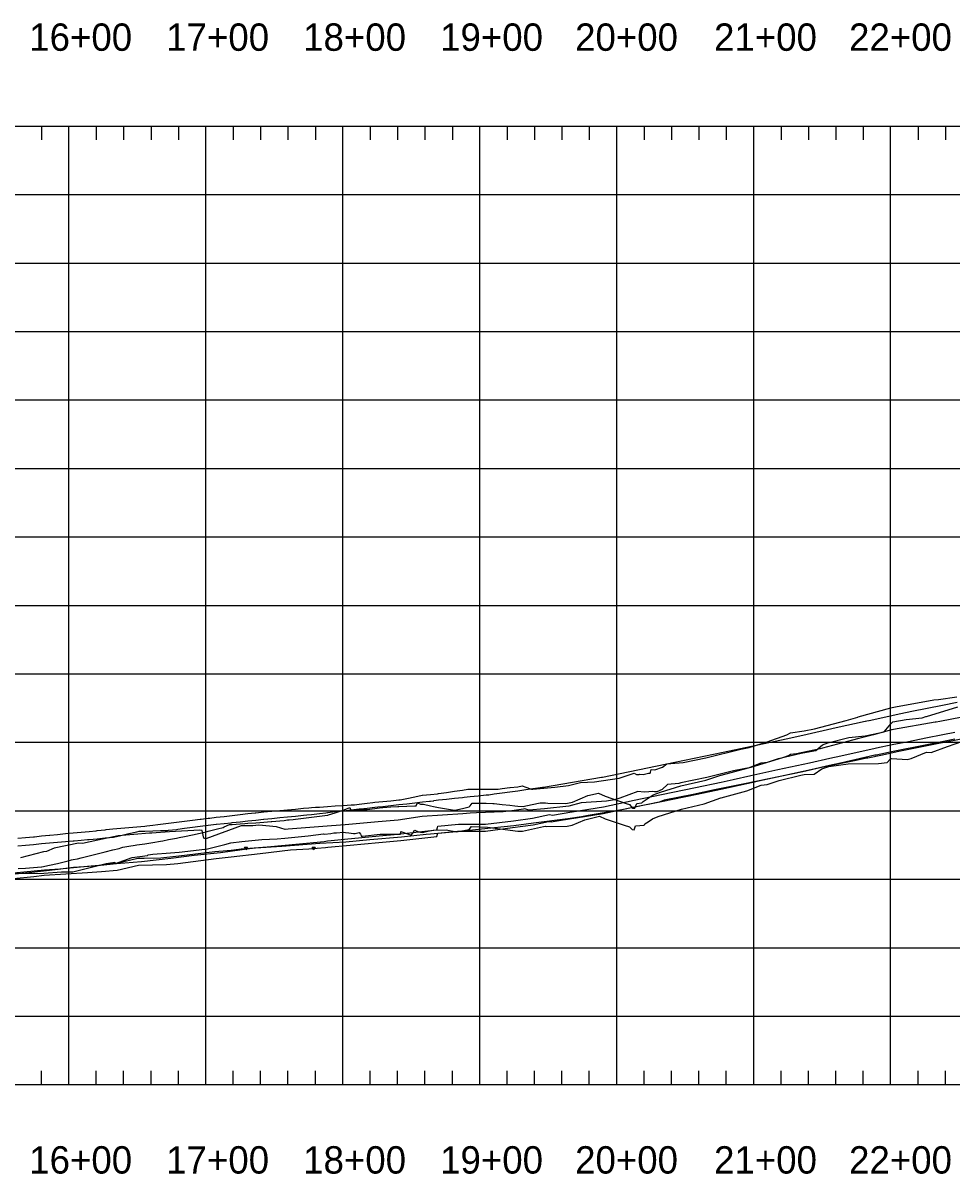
# Model space of a CAD drawing. Extents: x 704797 to 712284, y 374940 to 376945.
# Drawn here: x 708700 to 709378, y 375160 to 376001 of the extents above; entities that cross this region are included whole.
import ezdxf

# ---------------------------------------------------------------- set-up
doc = ezdxf.new("R2010")
doc.units = 0
for name, color, linetype in [('10', 7, 'Continuous'), ('12', 7, 'Continuous'), ('13', 7, 'Continuous'), ('61', 7, 'Continuous'), ('63', 7, 'Continuous'), ('Existing', 7, 'Continuous')]:
    doc.layers.add(name, color=color, linetype=linetype)

msp = doc.modelspace()

# ---------------------------------------------------------------- linework, layer by layer
at = {"layer": '10'}
for points in [[(709393.54, 375495.16), (709369.47, 375490.67), (709366.81, 375490.26), (709366.1, 375490.23), (709335.81, 375484.83), (709334.72, 375484.55), (709334.33, 375484.52), (709321.11, 375480.82), (709310.39, 375478.29), (709310.38, 375478.28), (709305.75, 375476.92), (709283.92, 375471.09), (709282.32, 375470.64), (709264.9, 375467.08), (709260.62, 375466.43), (709259.54, 375465.84), (709254.8, 375464.05), (709231.69, 375457.05), (709218.97, 375454.51), (709199.47, 375449.79), (709180.52, 375445.9), (709179.12, 375445.45), (709170.84, 375444.73), (709166.75, 375440.94), (709162.97, 375439.28), (709161.22, 375439.28), (709159.61, 375439.45), (709157.25, 375439.16), (709153.72, 375439.1), (709149.2, 375439.62), (709135.89, 375434.6), (709132.03, 375433.32), (709126.32, 375432.52), (709107.84, 375431.23), (709098.8, 375428.93), (709080.98, 375426.9), (709069.63, 375425.9), (709066.71, 375426.85), (709065.54, 375426.54), (709055.47, 375425.15), (709054.86, 375425.1), (709050.83, 375424.64), (709031.41, 375423.87), (709026.58, 375423.69), (709021.45, 375423.3), (708991.62, 375421.22), (708974.2, 375418.48), (708959.48, 375417.44), (708940.68, 375415.68), (708935.43, 375415.08), (708925.51, 375414.52), (708900.25, 375412.44), (708893.89, 375411.93), (708891.54, 375411.76), (708885.34, 375413.69), (708872.3, 375415.02), (708868.06, 375414.55), (708866.38, 375414.49), (708859.59, 375414.38), (708833.69, 375404.85), (708832.29, 375405.4), (708831.03, 375410.97), (708829.33, 375411.18), (708807.14, 375410.08), (708794.18, 375409.21), (708794.05, 375409.18), (708793.94, 375409.2), (708793.49, 375409.18), (708792.55, 375409.19), (708769.64, 375407.18), (708754.79, 375404.06), (708743.65, 375401.57), (708740.72, 375401.7), (708723.01, 375398.12), (708717.32, 375395.81), (708715.31, 375395.49), (708698.44, 375391.04)], [(708695.19, 375379.52), (708715.38, 375379.96), (708728.25, 375380.8), (708736.67, 375380.83), (708760.88, 375386.95), (708767.39, 375387.91), (708767.72, 375386.86), (708779.87, 375391.35), (708791.1, 375392.78), (708791.69, 375393.38), (708795.13, 375393.8), (708807.83, 375394.7), (708814.36, 375395.1), (708820.47, 375395.9), (708834.87, 375397.66), (708847.68, 375400.87), (708851.92, 375402.15), (708859.98, 375403.01), (708874.65, 375404.43), (708885.9, 375405.02), (708891.4, 375405.5), (708908.41, 375407.21), (708919.53, 375408.5), (708920.37, 375408.46), (708925.02, 375408.74), (708927.17, 375409.26), (708929.13, 375409.32), (708934.24, 375409.74), (708935.7, 375409.55), (708938.21, 375409.4), (708941.46, 375408.79), (708941.9, 375408.84), (708942.76, 375408.76), (708945.77, 375409.65), (708946.58, 375408.31), (708947.05, 375407.36), (708947.18, 375406.91), (708948.13, 375406.99), (708960.88, 375408.34), (708972.75, 375408.44), (708975.65, 375408.26), (708975.96, 375409.57), (708976.13, 375410.39), (708980.87, 375408.55), (708983.64, 375407.63), (708984.94, 375409), (708985.16, 375409.39), (708985.84, 375411.08), (708986.28, 375411.28), (708988.98, 375410.16), (708991.83, 375409.64), (708995.89, 375410.47), (708999.8, 375411.21), (709009.21, 375411.57), (709016.73, 375410.07), (709025.97, 375411.81), (709027.75, 375413.88), (709039.43, 375413.44), (709061.38, 375410.64), (709064.95, 375410.46), (709080.27, 375414.07), (709081.66, 375414.11), (709082.32, 375413.98), (709097.46, 375414.09), (709101.25, 375414.85), (709110.39, 375418.9), (709121.17, 375421.43), (709125.31, 375419.59), (709125.33, 375419.59), (709128.26, 375418.62), (709139.14, 375414.97), (709143.1, 375413.83), (709144.89, 375411.65), (709146.32, 375411.55), (709147.48, 375414.48), (709153.62, 375415.04), (709154.28, 375415.8), (709156.56, 375417.4), (709159.85, 375419.68), (709163.95, 375421.17), (709180.92, 375426.63), (709197.42, 375430.45), (709209.8, 375434.89), (709210.01, 375434.88), (709228.59, 375439.92), (709239.06, 375444.15), (709243.52, 375444.72), (709252.35, 375447.54), (709268.18, 375451.42), (709270.5, 375451.88), (709277.83, 375452.11), (709283.43, 375456.16), (709288.54, 375457.8), (709302.59, 375459.77), (709324.91, 375460.06), (709331.08, 375460.61), (709333.45, 375463.12), (709334.43, 375463.66), (709345.85, 375462.9), (709348.62, 375463.55), (709359.79, 375468.22), (709363.25, 375467.97), (709375.15, 375472.28), (709386.33, 375476.25)]]:
    msp.add_lwpolyline(points, dxfattribs=at)
at = {"layer": '12'}
for points in [[(708693.31, 375380.02), (708716.04, 375382.23), (708727.08, 375383.15), (708747.38, 375385.03), (708758.23, 375386.03), (708769.63, 375387.34), (708784.09, 375390.77), (708788.59, 375390.92), (708800.74, 375391.19), (708814.08, 375392.52), (708840.37, 375395.63), (708852.29, 375396.79), (708859.46, 375397.56), (708878.44, 375399.17), (708899.33, 375400.99), (708920.13, 375402.95), (708922.58, 375403.53), (708925.19, 375403.81), (708934.97, 375404.72), (708960.27, 375407.08), (708973.84, 375408.45), (709002.34, 375411.62), (709002.85, 375413.26), (709003.09, 375414.11), (709018.07, 375415.62), (709030.88, 375415.68), (709037.89, 375415.64), (709058.37, 375418.17), (709072.15, 375420), (709084.6, 375422.71), (709086.71, 375422.28), (709100.92, 375424.7), (709101.08, 375424.7), (709123.98, 375428.42), (709146.5, 375433.28), (709166.36, 375437.31), (709191.11, 375442.42), (709209.95, 375446.3), (709218.71, 375448.33), (709231.59, 375451.3), (709251.35, 375455.48), (709274.38, 375460.44), (709289.22, 375463.75), (709297.43, 375465.6), (709322.31, 375471.2), (709323.27, 375471.35), (709334.86, 375473.85), (709346.72, 375476.13), (709359.32, 375478.6), (709371.86, 375481.1), (709380.57, 375482.81)], [(708693.32, 375375.9), (708708.03, 375377.45), (708715.75, 375378.36), (708747.42, 375380.46), (708757.55, 375381.12), (708768.94, 375382.1), (708784.63, 375385.62), (708805.09, 375386.13), (708813.29, 375387.03), (708813.34, 375387.04), (708841.31, 375390.62), (708852.28, 375391.78), (708873.45, 375394.23), (708895.47, 375396.87), (708908.92, 375397.71), (708920.99, 375398.58), (708922.78, 375398.97), (708939.05, 375400.42), (708960.08, 375402.28), (708976.05, 375403.82), (709002.3, 375406.64), (709002.81, 375408.26), (709003.04, 375409.09), (709017.48, 375410.57), (709037.82, 375410.58), (709057.67, 375413.12), (709072.81, 375415.23), (709084, 375417.7), (709085.79, 375417.32), (709093.02, 375418.59), (709103.85, 375420.4), (709103.98, 375420.4), (709123.89, 375423.55), (709145.51, 375428.14), (709166.35, 375432.3), (709192.38, 375437.59), (709209.81, 375441.13), (709234.22, 375446.7), (709237.19, 375447.33), (709250.73, 375450.22), (709275.37, 375455.58), (709289.07, 375458.67), (709297.13, 375460.5), (709322.13, 375466.2), (709323.12, 375466.35), (709335.53, 375469.05), (709358.78, 375473.57), (709372.3, 375476.25), (709380.62, 375477.87)]]:
    msp.add_lwpolyline(points, dxfattribs=at)
for points in [[(708863.01, 375396.86), (708862.01, 375398.86), (708864.01, 375398.86)], [(708912.44, 375396.97), (708911.44, 375398.97), (708913.44, 375398.97)]]:
    msp.add_lwpolyline(points, close=True, dxfattribs=at)
at = {"layer": '13'}
msp.add_lwpolyline([(709389.1, 375478.49), (709367.65, 375474.26), (709356.61, 375472.12), (709338.56, 375468.5), (709327.77, 375466.16), (709317.12, 375463.95), (709316.2, 375463.83), (709316.15, 375463.93), (709308.57, 375462.24), (709283.29, 375456.99), (709269.68, 375453.93), (709244.74, 375448.86), (709226.94, 375445.1), (709225.78, 375444.87), (709205.07, 375440.65), (709189.47, 375437.4), (709168.32, 375433.08), (709164.7, 375431.78), (709156.43, 375429.98), (709137.42, 375426.05), (709112.76, 375421.92), (709108.09, 375421.12), (709097.97, 375419.44), (709072.95, 375416.4), (709058.66, 375414.43), (709035.02, 375412.04), (709019.64, 375410.4), (708997.76, 375408.35), (708994.51, 375408.04), (708976.47, 375406.17), (708953.41, 375404.23), (708935.83, 375402.48), (708916.9, 375401.47), (708889.29, 375399.35), (708870.06, 375398.06), (708865.61, 375397.53), (708844.35, 375394.85), (708825.21, 375392.75), (708808.1, 375390.56), (708786.7, 375388.08), (708768.39, 375386.62), (708752.15, 375385.03), (708737.11, 375383.92), (708725.82, 375382.66), (708704.38, 375380.21), (708689.31, 375378.72)], dxfattribs=at)
at = {"layer": '61'}
for p, q in [((708133.69, 375925.47), (712133.69, 375925.47)), ((708713.69, 375925.47), (708713.69, 375915.47)), ((708733.69, 375225.47), (708733.69, 375925.47)), ((708753.69, 375925.47), (708753.69, 375915.47)), ((708773.69, 375925.47), (708773.69, 375915.47)), ((708793.69, 375925.47), (708793.69, 375915.47)), ((708813.69, 375925.47), (708813.69, 375915.47)), ((708833.69, 375225.47), (708833.69, 375925.47)), ((708853.69, 375925.47), (708853.69, 375915.47)), ((708873.69, 375925.47), (708873.69, 375915.47)), ((708893.69, 375925.47), (708893.69, 375915.47)), ((708913.69, 375925.47), (708913.69, 375915.47)), ((708933.69, 375225.47), (708933.69, 375925.47)), ((708953.69, 375925.47), (708953.69, 375915.47)), ((708973.69, 375925.47), (708973.69, 375915.47)), ((708993.69, 375925.47), (708993.69, 375915.47)), ((709013.69, 375925.47), (709013.69, 375915.47)), ((709033.69, 375225.47), (709033.69, 375925.47)), ((709053.69, 375925.47), (709053.69, 375915.47)), ((709073.69, 375925.47), (709073.69, 375915.47)), ((709093.69, 375925.47), (709093.69, 375915.47)), ((709113.69, 375925.47), (709113.69, 375915.47)), ((709133.69, 375225.47), (709133.69, 375925.47)), ((709153.69, 375925.47), (709153.69, 375915.47)), ((709173.69, 375925.47), (709173.69, 375915.47)), ((709193.69, 375925.47), (709193.69, 375915.47)), ((709213.69, 375925.47), (709213.69, 375915.47)), ((709233.69, 375225.47), (709233.69, 375925.47)), ((709253.69, 375925.47), (709253.69, 375915.47)), ((709273.69, 375925.47), (709273.69, 375915.47)), ((709293.69, 375925.47), (709293.69, 375915.47)), ((709313.69, 375925.47), (709313.69, 375915.47)), ((709333.69, 375225.47), (709333.69, 375925.47)), ((709353.69, 375925.47), (709353.69, 375915.47)), ((709373.69, 375925.47), (709373.69, 375915.47)), ((708133.69, 375875.47), (712133.69, 375875.47)), ((708133.69, 375825.47), (712133.69, 375825.47)), ((708133.69, 375775.47), (712133.69, 375775.47)), ((708133.69, 375725.47), (712133.69, 375725.47)), ((708133.69, 375675.47), (712133.69, 375675.47)), ((708133.69, 375625.47), (712133.69, 375625.47)), ((708133.69, 375575.47), (712133.69, 375575.47)), ((708133.69, 375525.47), (712133.69, 375525.47)), ((708133.69, 375475.47), (712133.69, 375475.47)), ((708133.69, 375425.47), (712133.69, 375425.47)), ((708133.69, 375375.47), (712133.69, 375375.47)), ((708133.69, 375325.47), (712133.69, 375325.47)), ((708133.69, 375275.47), (712133.69, 375275.47)), ((708713.69, 375225.47), (708713.69, 375235.47)), ((708753.69, 375225.47), (708753.69, 375235.47)), ((708773.69, 375225.47), (708773.69, 375235.47)), ((708793.69, 375225.47), (708793.69, 375235.47)), ((708813.69, 375225.47), (708813.69, 375235.47)), ((708853.69, 375225.47), (708853.69, 375235.47)), ((708873.69, 375225.47), (708873.69, 375235.47)), ((708893.69, 375225.47), (708893.69, 375235.47)), ((708913.69, 375225.47), (708913.69, 375235.47)), ((708953.69, 375225.47), (708953.69, 375235.47)), ((708973.69, 375225.47), (708973.69, 375235.47)), ((708993.69, 375225.47), (708993.69, 375235.47)), ((709013.69, 375225.47), (709013.69, 375235.47)), ((709053.69, 375225.47), (709053.69, 375235.47)), ((709073.69, 375225.47), (709073.69, 375235.47)), ((709093.69, 375225.47), (709093.69, 375235.47)), ((709113.69, 375225.47), (709113.69, 375235.47)), ((709153.69, 375225.47), (709153.69, 375235.47)), ((709173.69, 375225.47), (709173.69, 375235.47)), ((709193.69, 375225.47), (709193.69, 375235.47)), ((709213.69, 375225.47), (709213.69, 375235.47)), ((709253.69, 375225.47), (709253.69, 375235.47)), ((709273.69, 375225.47), (709273.69, 375235.47)), ((709293.69, 375225.47), (709293.69, 375235.47)), ((709313.69, 375225.47), (709313.69, 375235.47)), ((709353.69, 375225.47), (709353.69, 375235.47)), ((709373.69, 375225.47), (709373.69, 375235.47)), ((708133.69, 375225.47), (712133.69, 375225.47))]:
    msp.add_line(p, q, dxfattribs=at)
at = {"layer": '63'}
for points in [[(708696.36, 375405.39), (708702.16, 375405.92), (708707.95, 375406.45), (708708.69, 375406.51), (708713.75, 375407.04), (708719.55, 375407.65), (708719.87, 375407.68), (708725.34, 375408.22), (708731.14, 375408.79), (708736.94, 375409.34), (708742.73, 375409.89), (708748.53, 375410.43), (708753.74, 375410.91), (708754.33, 375410.98), (708760.12, 375411.63), (708760.92, 375411.72), (708765.92, 375412.18), (708771.72, 375412.71), (708777.52, 375413.22), (708783.31, 375413.73), (708789.11, 375414.23), (708790.54, 375414.36), (708794.91, 375414.89), (708798.75, 375415.35), (708800.7, 375415.61), (708806.5, 375416.37), (708812.3, 375417.12), (708818.09, 375417.87), (708823.89, 375418.61), (708829.69, 375419.34), (708830.22, 375419.41), (708835.48, 375419.97), (708836.58, 375420.09), (708841.28, 375420.66), (708847.08, 375421.35), (708852.87, 375422.04), (708858.67, 375422.72), (708864.47, 375423.39), (708869.74, 375423.99), (708870.26, 375424.04), (708876.06, 375424.64), (708881.6, 375425.2), (708881.86, 375425.22), (708887.65, 375425.73), (708893.45, 375426.24), (708899.25, 375426.74), (708905.04, 375427.25), (708908.8, 375427.57), (708910.84, 375427.75), (708913.85, 375428.02), (708916.64, 375428.2), (708922.43, 375428.58), (708928.23, 375428.95), (708934.03, 375429.32), (708939.82, 375429.69), (708942.27, 375429.84), (708945.62, 375430.25), (708951.42, 375430.96), (708955.6, 375431.47), (708957.21, 375431.63), (708963.01, 375432.22), (708968.81, 375432.79), (708974.6, 375433.35), (708975.61, 375433.45), (708980.4, 375434.44), (708986.2, 375435.62), (708991.74, 375436.73), (708991.99, 375436.76), (708997.79, 375437.4), (709002.74, 375437.93), (709003.59, 375438.06), (709009.38, 375438.89), (709015.18, 375439.7), (709017.24, 375439.97), (709020.98, 375440.57), (709024.91, 375441.17), (709026.77, 375441.16), (709031.11, 375441.11), (709032.57, 375441.14), (709038.37, 375441.22), (709044.16, 375441.27), (709046.75, 375441.28), (709047.12, 375441.28), (709049.96, 375441.64), (709055.76, 375442.35), (709055.86, 375442.36), (709061.47, 375442.9), (709061.55, 375442.92), (709064.75, 375443.57), (709067.35, 375442.63), (709071.47, 375441.19), (709071.57, 375441.18), (709071.71, 375441.16), (709072.45, 375441.19), (709088.43, 375442.57), (709098.45, 375443.83), (709107.19, 375446.07), (709117.41, 375446.52), (709135.36, 375449.34), (709146.44, 375452.99), (709148.23, 375451.93), (709150, 375452.06), (709150.28, 375452.27), (709153.07, 375451.98), (709156.81, 375452.84), (709158.19, 375453), (709158.36, 375453.57), (709158.81, 375455.66), (709161.58, 375455.42), (709167.2, 375457.18), (709170.21, 375459.68), (709182.18, 375460.72), (709198.82, 375464.19), (709224.27, 375470.44), (709230.32, 375471.66), (709243.6, 375475.68), (709257.81, 375480.91), (709260.62, 375482.39), (709270.54, 375483.76), (709278.06, 375485.22), (709301.26, 375491.47), (709309.74, 375493.83), (709309.99, 375493.95), (709333.82, 375500.71), (709334.68, 375500.79), (709337.11, 375501.42), (709365.27, 375506.55), (709368.69, 375506.7), (709381.98, 375508.78)], [(708696.75, 375383.23), (708702.16, 375383.62), (708707.95, 375384.02), (708713.75, 375384.4), (708713.99, 375384.42), (708719.55, 375385.71), (708725.34, 375387.06), (708731.14, 375388.42), (708733.16, 375388.89), (708735.6, 375389.62), (708736.94, 375389.84), (708740.07, 375390.37), (708742.73, 375391.03), (708748.53, 375392.47), (708754.33, 375393.91), (708760.12, 375395.36), (708765.92, 375396.81), (708770.48, 375397.96), (708771.72, 375398.39), (708773.23, 375398.91), (708777.52, 375399.57), (708782.21, 375400.29), (708783.31, 375400.47), (708789.11, 375401.41), (708794.91, 375402.35), (708800.7, 375403.28), (708802.31, 375403.54), (708806.5, 375404.38), (708812.3, 375405.53), (708814.14, 375405.9), (708818.09, 375406.74), (708823.89, 375407.96), (708829.69, 375409.18), (708834.06, 375410.09), (708835.48, 375410.45), (708841.28, 375411.9), (708842.23, 375412.14), (708846.29, 375413.35), (708847.08, 375413.69), (708850.98, 375415.37), (708852.87, 375415.51), (708858.67, 375415.94), (708862.09, 375416.18), (708864.47, 375416.35), (708870.26, 375416.76), (708876.06, 375417.15), (708881.33, 375417.5), (708881.86, 375417.56), (708887.65, 375418.14), (708890.95, 375418.46), (708893.45, 375418.79), (708894.6, 375418.94), (708897.53, 375419.1), (708899.25, 375419.32), (708905.04, 375420.07), (708910.84, 375420.81), (708916.64, 375421.54), (708922.43, 375422.26), (708922.88, 375422.32), (708923.31, 375422.4), (708928.23, 375423.99), (708933.34, 375425.64), (708934.03, 375425.87), (708935.99, 375426.5), (708938.88, 375427.77), (708939.12, 375427.11), (708939.67, 375425.71), (708939.82, 375425.72), (708939.85, 375425.72), (708945.62, 375426.23), (708947, 375426.35), (708950.86, 375426.38), (708951.42, 375426.44), (708957.21, 375427.14), (708962.28, 375427.74), (708963.01, 375427.8), (708968.81, 375428.22), (708973.8, 375428.58), (708974.6, 375428.61), (708980.4, 375428.85), (708986.2, 375429.08), (708986.71, 375429.1), (708987.28, 375429.08), (708987.48, 375429.62), (708988.13, 375431.31), (708990.37, 375430.33), (708991.99, 375430.21), (708992.52, 375430.17), (708997.79, 375428.97), (708999.87, 375428.49), (709003.59, 375427.88), (709009.38, 375426.91), (709015.18, 375425.92), (709015.47, 375425.86), (709020.98, 375427.16), (709026.08, 375428.33), (709026.77, 375429.17), (709028.25, 375430.93), (709032.57, 375430.95), (709038.37, 375430.93), (709043.24, 375430.87), (709044.16, 375430.78), (709049.96, 375430.14), (709055.76, 375429.45), (709059.33, 375428.98), (709061.55, 375428.86), (709065.5, 375428.6), (709067.35, 375429), (709077.87, 375431.29), (709081.72, 375431.35), (709083.52, 375430.96), (709096.46, 375430.87), (709101.32, 375431.78), (709112.71, 375436.65), (709120.49, 375438.32), (709125.22, 375436.14), (709125.24, 375436.14), (709140.71, 375430.78), (709143.03, 375430.09), (709145.25, 375427.36), (709147.02, 375427.23), (709148.44, 375430.84), (709152.13, 375431.13), (709153.02, 375432.12), (709160.38, 375437.16), (709165.72, 375439.04), (709180.51, 375443.67), (709198.8, 375447.74), (709209.65, 375451.54), (709209.88, 375451.53), (709229.88, 375456.79), (709239.16, 375460.49), (709243.85, 375461.05), (709251.85, 375463.55), (709268.38, 375467.49), (709279.16, 375469.53), (709284, 375473.49), (709287.92, 375475.18), (709303.18, 375478.9), (709314.98, 375480.29), (709328.89, 375483.19), (709333.71, 375489.06), (709335.24, 375490.44), (709344.99, 375492.04), (709356.63, 375493.29), (709359.28, 375494.28), (709359.95, 375494.2), (709382.85, 375501.39)]]:
    msp.add_lwpolyline(points, dxfattribs=at)
at = {"layer": 'Existing'}
msp.add_lwpolyline([(708696.36, 375399.8), (708702.16, 375400.36), (708707.95, 375400.9), (708713.75, 375401.43), (708719.55, 375401.96), (708725.34, 375402.47), (708731.14, 375402.98), (708736.94, 375403.48), (708737.59, 375403.54), (708742.73, 375404.01), (708747.31, 375404.43), (708748.53, 375404.54), (708754.33, 375405.06), (708760.12, 375405.57), (708760.88, 375405.64), (708765.92, 375406.18), (708766.3, 375406.22), (708771.72, 375407.48), (708777.52, 375408.83), (708783.31, 375410.17), (708784.93, 375410.54), (708789.11, 375410.66), (708794.91, 375410.83), (708800.7, 375410.99), (708805.71, 375411.13), (708806.5, 375411.22), (708812.3, 375411.89), (708813.23, 375411.99), (708818.09, 375412.63), (708823.89, 375413.39), (708829.69, 375414.13), (708835.48, 375414.86), (708841.28, 375415.58), (708841.55, 375415.62), (708847.08, 375416.18), (708852.11, 375416.69), (708852.87, 375416.77), (708858.67, 375417.4), (708864.47, 375418.01), (708870.26, 375418.62), (708875.79, 375419.2), (708876.06, 375419.23), (708881.86, 375419.84), (708887.65, 375420.45), (708893.45, 375421.04), (708899.25, 375421.63), (708905.04, 375422.21), (708907.43, 375422.44), (708910.84, 375422.8), (708916.64, 375423.4), (708921.41, 375423.89), (708922.43, 375424.13), (708922.9, 375424.25), (708928.23, 375424.85), (708934.03, 375425.5), (708939.82, 375426.14), (708945.62, 375426.78), (708949.15, 375427.16), (708951.42, 375427.41), (708957.21, 375428.03), (708959.2, 375428.24), (708963.01, 375428.68), (708968.81, 375429.33), (708974.6, 375429.98), (708980.4, 375430.62), (708986.2, 375431.26), (708991.99, 375431.89), (708996.9, 375432.41), (708997.79, 375432.52), (709000.17, 375432.79), (709000.22, 375432.97), (709000.25, 375433.06), (709003.59, 375433.4), (709009.38, 375433.98), (709015.18, 375434.56), (709020.98, 375435.15), (709022.3, 375435.28), (709026.77, 375435.76), (709032.57, 375436.37), (709038.37, 375436.98), (709039.37, 375437.09), (709040.39, 375437.19), (709044.16, 375437.71), (709049.96, 375438.5), (709055.76, 375439.3), (709061.55, 375440.1), (709067.35, 375440.89), (709079.61, 375442.58), (709080.2, 375442.66), (709122.67, 375449.9), (709123.37, 375450.02), (709169.02, 375459.38), (709169.05, 375459.39), (709169.07, 375459.39), (709169.16, 375459.41), (709211.41, 375468.17), (709257.31, 375477.92), (709257.52, 375477.96), (709269.5, 375480.67), (709293.98, 375486.16), (709315.06, 375490.93), (709315.29, 375490.99), (709316.35, 375491.15), (709317.87, 375491.36), (709318, 375491.38), (709341.22, 375496.46), (709349.16, 375498.18), (709349.27, 375498.2), (709371.62, 375502.59), (709382.14, 375504.65)], dxfattribs=at)

# ---------------------------------------------------------------- texts
at = {"layer": '61'}
for s, p in [('16+00', (708704.77, 375980.47)), ('17+00', (708804.77, 375980.47)), ('18+00', (708904.77, 375980.47)), ('19+00', (709004.77, 375980.47)), ('20+00', (709103.32, 375980.47)), ('21+00', (709204.77, 375980.47)), ('22+00', (709303.32, 375980.47)), ('16+00', (708704.77, 375160.47)), ('17+00', (708804.77, 375160.47)), ('18+00', (708904.77, 375160.47)), ('19+00', (709004.77, 375160.47)), ('20+00', (709103.32, 375160.47)), ('21+00', (709204.77, 375160.47)), ('22+00', (709303.32, 375160.47))]:
    msp.add_text(s, height=20, dxfattribs=at).set_placement(p)

doc.saveas('drawing.dxf')
